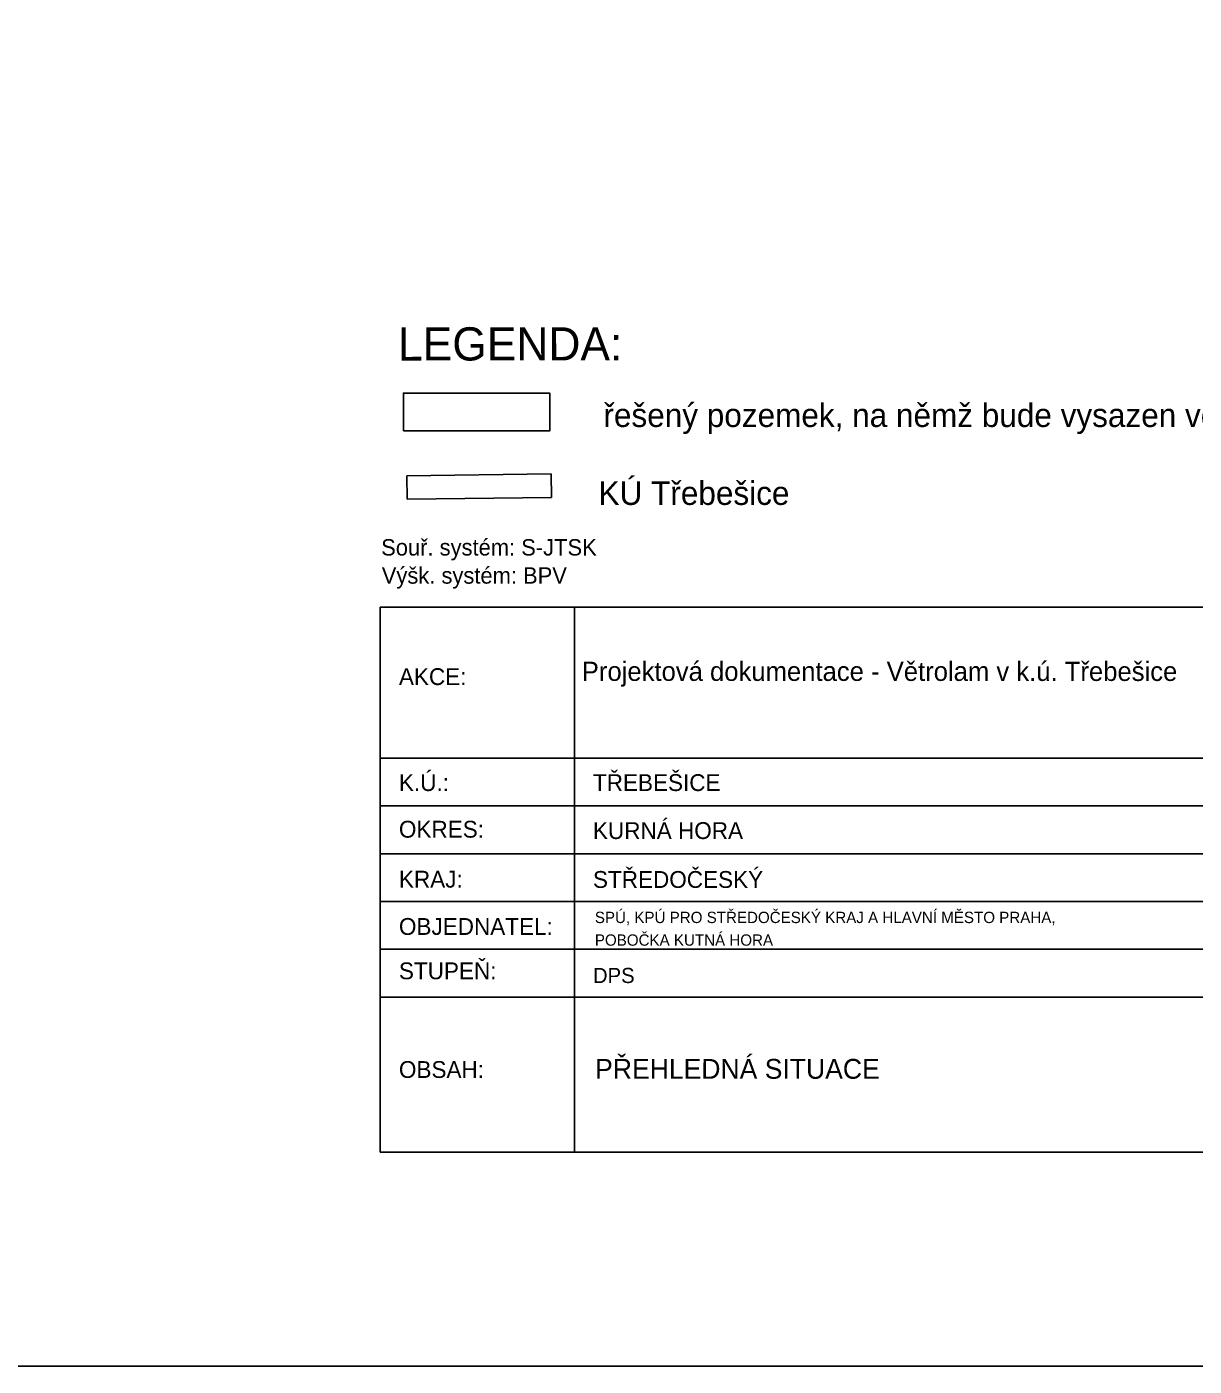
# Model space of a CAD drawing. Extents: x -680147 to -675947, y -1070829 to -1067859.
# Drawn here: x -678041 to -676747, y -1070829 to -1069344 of the extents above; entities that cross this region are included whole.
import ezdxf

# ---------------------------------------------------------------- set-up
doc = ezdxf.new("R2010")
doc.units = 0
doc.layers.add('LEGENDA', color=7, linetype='Continuous')

msp = doc.modelspace()

# ---------------------------------------------------------------- linework, layer by layer
at = {"layer": 'LEGENDA'}
for p, q in [((-677460.1, -1069839.4), (-677619.9, -1069841.4)), ((-677619.6, -1069867.6), (-677619.9, -1069841.4)), ((-677459.8, -1069865.6), (-677460.1, -1069839.4)), ((-677459.8, -1069865.6), (-677619.6, -1069867.6)), ((-677649.5, -1069987), (-676127, -1069987)), ((-677649.5, -1070591.5), (-677649.5, -1069987)), ((-677434, -1070591.5), (-677434, -1069987)), ((-677649.5, -1070154.7), (-676127, -1070154.7)), ((-677649.5, -1070207.6), (-676127, -1070207.6)), ((-677649.5, -1070260.6), (-676127, -1070260.6)), ((-677649.5, -1070313.5), (-676127, -1070313.5)), ((-677649.5, -1070366.5), (-676127, -1070366.5)), ((-677649.5, -1070419.4), (-676273.3, -1070419.4)), ((-677649.5, -1070591.5), (-676127, -1070591.5))]:
    msp.add_line(p, q, dxfattribs=at)
msp.add_lwpolyline([(-675946.7, -1070828.7), (-680146.7, -1070828.7), (-680146.7, -1067858.7), (-675946.7, -1067858.7)], close=True, dxfattribs=at)
for points in [[(-677623.8, -1069791.8), (-677461.7, -1069791.8), (-677461.7, -1069749.8), (-677623.8, -1069749.8), (-677623.8, -1069791.8)], [(-677461.7, -1069749.8), (-677623.8, -1069749.8), (-677623.8, -1069791.8)], [(-677623.8, -1069791.8), (-677461.7, -1069791.8), (-677461.7, -1069749.8)]]:
    msp.add_lwpolyline(points, dxfattribs=at)

# ---------------------------------------------------------------- texts
for s, height, rotation, p in [('LEGENDA:', 36.77, 0.0213, (-677629.8, -1069713.7)), ('řešený pozemek, na němž bude vysazen větrolam', 26.125, 359.9984, (-677402.1, -1069787.4)), ('KÚ Třebešice', 26.125, 359.9984, (-677407.5, -1069873.8)), ('Souř. systém: S-JTSK', 18.168, 0, (-677648.5, -1069929.9)), ('Výšk. systém: BPV', 18.168, 0, (-677647.8, -1069961.1)), ('Projektová dokumentace - Větrolam v k.ú. Třebešice', 21.25, 359.9942, (-677426.1, -1070068.9)), ('AKCE:', 18.66, 0, (-677628.8, -1070073.5)), ('K.Ú.:', 18.66, 0, (-677628.8, -1070191)), ('TŘEBEŠICE', 18.66, 0, (-677413.7, -1070191)), ('OKRES:', 18.66, 0, (-677628.8, -1070242.7)), ('KURNÁ HORA', 18.66, 0, (-677413.7, -1070244.2)), ('KRAJ:', 18.66, 0, (-677628.8, -1070298.1)), ('STŘEDOČESKÝ', 18.663, 0, (-677413.7, -1070298.4)), ('SPÚ, KPÚ PRO STŘEDOČESKÝ KRAJ A HLAVNÍ MĚSTO PRAHA, ', 12.542, 0, (-677411.6, -1070337.4)), ('OBJEDNATEL:', 18.663, 0, (-677628.8, -1070350.5)), ('POBOČKA KUTNÁ HORA', 12.542, 0, (-677411.6, -1070362.5)), ('STUPEŇ:', 18.66, 0, (-677628.8, -1070399.7)), ('DPS', 16.8, 0, (-677413.7, -1070403.9)), ('OBSAH:', 18.66, 0, (-677628.8, -1070509.1)), ('PŘEHLEDNÁ SITUACE', 22, 359.9942, (-677411.3, -1070510))]:
    msp.add_text(s, height=height, rotation=rotation, dxfattribs=at).set_placement(p)

doc.saveas('drawing.dxf')
